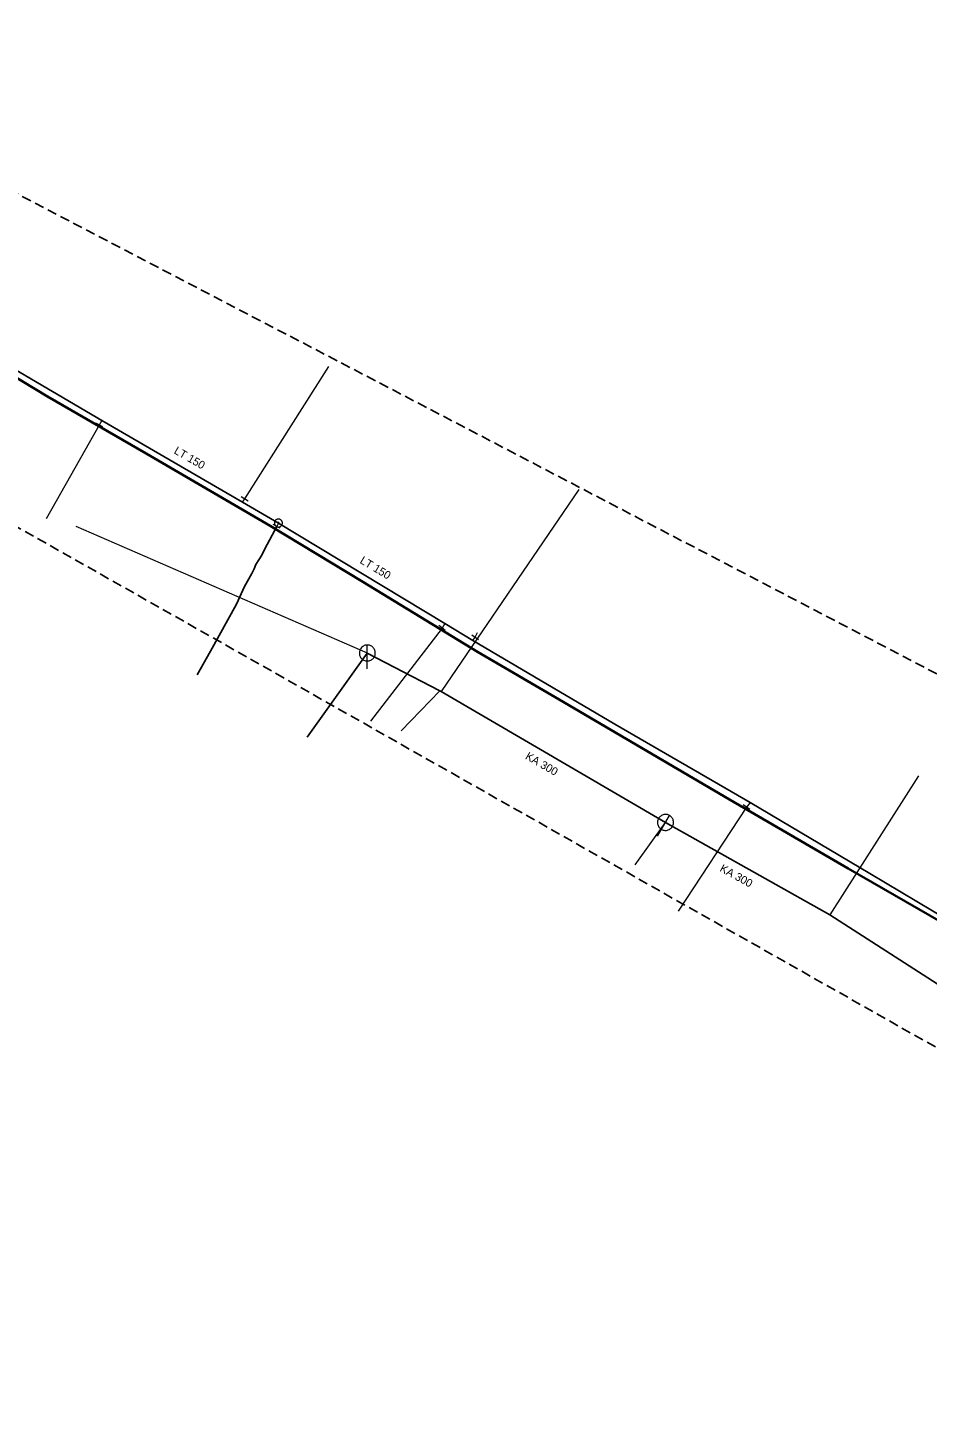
# Model space of a CAD drawing. Extents: x -749365 to -748625, y -965388 to -964881.
# Drawn here: x -749058.8 to -748946.2, y -965189.7 to -965017.6 of the extents above; entities that cross this region are included whole.
import ezdxf

# ---------------------------------------------------------------- set-up
doc = ezdxf.new("R2010")
doc.units = 0
doc.header["$LTSCALE"] = 0.4
doc.linetypes.add('MEDIUM_DASHED', pattern=[4.5, 3, -1.5])
for name, color, linetype, lineweight in [('1', 7, 'MEDIUM_DASHED', 25), ('11', 7, 'Continuous', 13), ('13', 7, 'Continuous', 13), ('14', 7, 'Continuous', 13), ('17', 7, 'Continuous', 25), ('22', 7, 'Continuous', 13), ('34', 7, 'Continuous', 13), ('47', 7, 'Continuous', 13)]:
    doc.layers.add(name, color=color, linetype=linetype, lineweight=lineweight)

msp = doc.modelspace()

# ---------------------------------------------------------------- linework, layer by layer
at = {"layer": '1'}
for points in [[(-748747.771, -965278.626), (-748913.896, -965162.751), (-749358.2, -964911.234)], [(-749094.514, -965020.387), (-748844.275, -965150.977), (-748843.645, -965151.367), (-748721.639, -965240.188)]]:
    msp.add_lwpolyline(points, dxfattribs=at)
at = {"layer": '11'}
for p, q in [((-748989.79, -965075.342), (-749007.033, -965100.565)), ((-749052.707, -965079.934), (-749016.26, -965095.773)), ((-749012.012, -965105.521), (-749007.197, -965100.494)), ((-748947.339, -965111.144), (-748958.403, -965128.502)), ((-748982.763, -965122.258), (-748978.969, -965116.949))]:
    msp.add_line(p, q, dxfattribs=at)
at = {"layer": '13'}
for p, q in [((-749031.594, -965076.487), (-749021.094, -965059.969)), ((-749049.776, -965067.279), (-749056.436, -965079.019)), ((-749006.919, -965092.655), (-749015.844, -965104.305)), ((-749002.77, -965093.798), (-749002.465, -965093.2)), ((-748968.859, -965115.046), (-748977.386, -965128.045))]:
    msp.add_line(p, q, dxfattribs=at)
at = {"layer": '14'}
for p, q in [((-749049.479, -965066.729), (-749049.776, -965067.279)), ((-749031.869, -965076.931), (-749031.594, -965076.487)), ((-749027.381, -965079.535), (-749027.593, -965079.958)), ((-749006.577, -965092.085), (-749006.919, -965092.655)), ((-749003.06, -965094.212), (-749002.77, -965093.798)), ((-748968.378, -965114.457), (-748968.859, -965115.046))]:
    msp.add_line(p, q, dxfattribs=at)
at = {"layer": '14', "lineweight": 25}
msp.add_line((-749023.766, -965106.3), (-749016.263, -965095.781), dxfattribs=at)
for points in [[(-749016.263, -965095.781), (-749007.197, -965100.493), (-749007.033, -965100.565), (-748978.969, -965116.949)], [(-748978.969, -965116.949), (-748958.403, -965128.502), (-748942.68, -965138.609)]]:
    msp.add_lwpolyline(points, dxfattribs=at)
at = {"layer": '17'}
for points in [[(-749027.381, -965079.535), (-749031.869, -965076.931), (-749049.479, -965066.729), (-749061.789, -965059.449), (-749067.474, -965056.055), (-749068.21, -965055.686), (-749076.839, -965050.738), (-749082.197, -965048.039), (-749087.923, -965044.562), (-749096.879, -965039.45), (-749099.415, -965038.059), (-749107.856, -965032.835)], [(-749027.593, -965079.958), (-749029.095, -965082.769), (-749029.46, -965083.531), (-749030.206, -965084.721), (-749030.412, -965085.261), (-749030.714, -965085.848), (-749031.619, -965087.483), (-749032.635, -965089.674), (-749035.873, -965095.532), (-749037.521, -965098.513)], [(-748847.466, -965188.465), (-748853.619, -965184.024), (-748860.449, -965179.484), (-748874.395, -965169.75), (-748883.27, -965164.229), (-748898.443, -965154.905), (-748902.451, -965152.696), (-748912.348, -965147.052), (-748917.379, -965144.189), (-748932.225, -965135.764), (-748939.709, -965131.511), (-748953.41, -965123.331), (-748968.378, -965114.457), (-748985.31, -965104.682), (-749003.06, -965094.212), (-749006.577, -965092.085), (-749027.381, -965079.535)]]:
    msp.add_lwpolyline(points, dxfattribs=at)
at = {"layer": '17', "lineweight": 35}
msp.add_lwpolyline([(-749068.54, -965056.298), (-749056.263, -965063.706), (-749043.934, -965070.85), (-749028.429, -965079.899), (-749016.84, -965086.884), (-749002.5, -965095.615), (-748992.287, -965101.595), (-748970.961, -965114.083), (-748956.145, -965122.709), (-748940.111, -965131.916), (-748933.02, -965136.308), (-748918.68, -965144.352), (-748906.641, -965151.253), (-748901.237, -965154.281)], dxfattribs=at)
at = {"layer": '22'}
for p, q in [((-749016.26, -965097.773), (-749016.259, -965094.773)), ((-748979.964, -965118.683), (-748978.471, -965116.082))]:
    msp.add_line(p, q, dxfattribs=at)
for points in [[(-749015.26, -965095.773), (-749015.265, -965095.664), (-749015.283, -965095.556), (-749015.313, -965095.45), (-749015.353, -965095.349), (-749015.405, -965095.252), (-749015.467, -965095.162), (-749015.539, -965095.079), (-749015.619, -965095.005), (-749015.707, -965094.939), (-749015.801, -965094.884), (-749015.901, -965094.839), (-749016.006, -965094.806), (-749016.113, -965094.784), (-749016.222, -965094.774), (-749016.332, -965094.776), (-749016.44, -965094.79), (-749016.547, -965094.815), (-749016.65, -965094.852), (-749016.748, -965094.901), (-749016.84, -965094.959), (-749016.926, -965095.028), (-749017.003, -965095.105), (-749017.072, -965095.191), (-749017.131, -965095.283), (-749017.179, -965095.381), (-749017.216, -965095.484), (-749017.242, -965095.591), (-749017.256, -965095.699), (-749017.259, -965095.809), (-749017.249, -965095.918), (-749017.228, -965096.025), (-749017.194, -965096.129), (-749017.15, -965096.229), (-749017.095, -965096.324), (-749017.029, -965096.412), (-749016.955, -965096.492), (-749016.872, -965096.564), (-749016.782, -965096.626), (-749016.686, -965096.678), (-749016.584, -965096.719), (-749016.479, -965096.749), (-749016.371, -965096.767), (-749016.261, -965096.773), (-749016.152, -965096.767), (-749016.044, -965096.749), (-749015.939, -965096.72), (-749015.837, -965096.679), (-749015.74, -965096.627), (-749015.65, -965096.565), (-749015.567, -965096.494), (-749015.492, -965096.414), (-749015.427, -965096.326), (-749015.371, -965096.232), (-749015.327, -965096.132), (-749015.293, -965096.028), (-749015.271, -965095.92), (-749015.261, -965095.811)], [(-748978.101, -965117.447), (-748978.052, -965117.349), (-748978.014, -965117.247), (-748977.988, -965117.14), (-748977.972, -965117.032), (-748977.969, -965116.922), (-748977.978, -965116.813), (-748977.999, -965116.705), (-748978.031, -965116.601), (-748978.075, -965116.5), (-748978.129, -965116.406), (-748978.193, -965116.317), (-748978.268, -965116.236), (-748978.35, -965116.164), (-748978.439, -965116.101), (-748978.536, -965116.048), (-748978.636, -965116.006), (-748978.742, -965115.975), (-748978.849, -965115.956), (-748978.959, -965115.949), (-748979.067, -965115.954), (-748979.176, -965115.971), (-748979.281, -965115.999), (-748979.384, -965116.039), (-748979.481, -965116.09), (-748979.571, -965116.151), (-748979.655, -965116.222), (-748979.731, -965116.302), (-748979.797, -965116.388), (-748979.853, -965116.483), (-748979.899, -965116.582), (-748979.934, -965116.686), (-748979.956, -965116.793), (-748979.968, -965116.901), (-748979.967, -965117.011), (-748979.954, -965117.12), (-748979.929, -965117.227), (-748979.893, -965117.33), (-748979.846, -965117.429), (-748979.789, -965117.522), (-748979.721, -965117.608), (-748979.645, -965117.686), (-748979.56, -965117.756), (-748979.467, -965117.816), (-748979.37, -965117.865), (-748979.267, -965117.903), (-748979.162, -965117.93), (-748979.053, -965117.945), (-748978.943, -965117.948), (-748978.834, -965117.939), (-748978.727, -965117.919), (-748978.622, -965117.887), (-748978.522, -965117.843), (-748978.426, -965117.79), (-748978.338, -965117.725), (-748978.257, -965117.651), (-748978.184, -965117.569), (-748978.121, -965117.479)]]:
    msp.add_lwpolyline(points, close=True, dxfattribs=at)
at = {"layer": '34'}
for p, q in [((-749049.336, -965067.516), (-749050.215, -965067.04)), ((-749032.019, -965076.224), (-749031.169, -965076.75)), ((-749027.145, -965080.181), (-749028.039, -965079.733)), ((-749006.521, -965092.958), (-749007.315, -965092.35)), ((-749003.186, -965093.521), (-749002.354, -965094.075)), ((-748968.44, -965115.319), (-748969.276, -965114.771))]:
    msp.add_line(p, q, dxfattribs=at)
at = {"layer": '47'}
for points in [[(-749027.604, -965079.982), (-749027.556, -965080.002), (-749027.506, -965080.018), (-749027.455, -965080.028), (-749027.403, -965080.034), (-749027.351, -965080.034), (-749027.298, -965080.027), (-749027.248, -965080.016), (-749027.198, -965079.999), (-749027.151, -965079.978), (-749027.105, -965079.952), (-749027.063, -965079.92), (-749027.025, -965079.885), (-749026.99, -965079.846), (-749026.959, -965079.803), (-749026.933, -965079.758), (-749026.913, -965079.71), (-749026.897, -965079.66), (-749026.886, -965079.608), (-749026.881, -965079.557), (-749026.881, -965079.505), (-749026.888, -965079.452), (-749026.899, -965079.401), (-749026.915, -965079.351), (-749026.936, -965079.304), (-749026.963, -965079.259), (-749026.995, -965079.217), (-749027.03, -965079.178), (-749027.069, -965079.144), (-749027.112, -965079.113), (-749027.157, -965079.087), (-749027.205, -965079.067), (-749027.255, -965079.051), (-749027.306, -965079.039), (-749027.358, -965079.035), (-749027.41, -965079.035), (-749027.462, -965079.041), (-749027.514, -965079.052), (-749027.563, -965079.068), (-749027.611, -965079.09), (-749027.656, -965079.117), (-749027.698, -965079.149), (-749027.737, -965079.183), (-749027.771, -965079.223), (-749027.802, -965079.266), (-749027.828, -965079.311), (-749027.848, -965079.359), (-749027.864, -965079.409), (-749027.875, -965079.459), (-749027.88, -965079.512), (-749027.88, -965079.564), (-749027.874, -965079.616), (-749027.863, -965079.667), (-749027.846, -965079.716), (-749027.824, -965079.764), (-749027.798, -965079.81), (-749027.766, -965079.852), (-749027.732, -965079.89), (-749027.692, -965079.925), (-749027.649, -965079.956)], [(-749027.417, -965079.608), (-749027.409, -965079.612), (-749027.401, -965079.614), (-749027.393, -965079.615), (-749027.385, -965079.616), (-749027.376, -965079.616), (-749027.367, -965079.615), (-749027.359, -965079.614), (-749027.351, -965079.611), (-749027.343, -965079.607), (-749027.335, -965079.603), (-749027.328, -965079.598), (-749027.322, -965079.592), (-749027.317, -965079.585), (-749027.311, -965079.579), (-749027.307, -965079.571), (-749027.303, -965079.563), (-749027.301, -965079.555), (-749027.3, -965079.547), (-749027.299, -965079.539), (-749027.299, -965079.53), (-749027.3, -965079.521), (-749027.301, -965079.513), (-749027.304, -965079.505), (-749027.308, -965079.496), (-749027.312, -965079.489), (-749027.317, -965079.482), (-749027.323, -965079.476), (-749027.33, -965079.471), (-749027.336, -965079.465), (-749027.344, -965079.461), (-749027.352, -965079.457), (-749027.36, -965079.455), (-749027.368, -965079.454), (-749027.376, -965079.453), (-749027.385, -965079.453), (-749027.393, -965079.453), (-749027.402, -965079.455), (-749027.41, -965079.458), (-749027.419, -965079.462), (-749027.426, -965079.466), (-749027.433, -965079.471), (-749027.439, -965079.477), (-749027.444, -965079.484), (-749027.45, -965079.49), (-749027.454, -965079.498), (-749027.458, -965079.506), (-749027.46, -965079.514), (-749027.461, -965079.522), (-749027.462, -965079.53), (-749027.462, -965079.539), (-749027.462, -965079.547), (-749027.46, -965079.556), (-749027.457, -965079.564), (-749027.453, -965079.572), (-749027.449, -965079.58), (-749027.444, -965079.587), (-749027.438, -965079.593), (-749027.431, -965079.598), (-749027.425, -965079.604)]]:
    msp.add_lwpolyline(points, close=True, dxfattribs=at)

# ---------------------------------------------------------------- texts
at = {"layer": '1'}
for s, rotation, p in [('LT 150', 330, (-749040.53, -965070.772)), ('LT 150', 329, (-749017.277, -965084.477)), ('KA 300', 330, (-748996.592, -965108.959)), ('KA 300', 331, (-748972.273, -965122.986))]:
    msp.add_text(s, height=1, rotation=rotation, dxfattribs=at).set_placement(p)

doc.saveas('drawing.dxf')
